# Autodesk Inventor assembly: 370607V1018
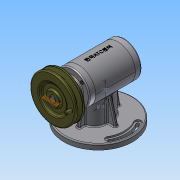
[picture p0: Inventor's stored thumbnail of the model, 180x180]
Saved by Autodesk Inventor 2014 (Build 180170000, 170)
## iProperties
Created: 2017-06
Part Number: 370607V1018
Document SubType Name: Assembly
Designer: NET
Mass: 1417.53 g
Surface Area: 1464.36 cm^2
Volume: 498.031 cm^3
Density: 2.84627 g/cm^3
Author: NET
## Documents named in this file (15)
- C:\Users\NET\Desktop\370607V1018\답안조립품.iam
- C:\Users\NET\Desktop\370607V1018\본체.ipt
- C:\Users\NET\Desktop\370607V1018\본체커버.ipt
- C:\Users\NET\Desktop\370607V1018\앞커버.ipt
- C:\Users\NET\Desktop\370607V1018\볼트 M3x0.5x8.ipt
- C:\Users\NET\Desktop\370607V1018\오일실 12 22 7.ipt
- C:\Users\NET\Desktop\370607V1018\베어링 6201.ipt
- C:\Users\NET\Desktop\370607V1018\뒤커버.ipt
- C:\Users\NET\Desktop\370607V1018\베어링 6202.ipt
- C:\Users\NET\Desktop\370607V1018\편심축.ipt
- C:\Users\NET\Desktop\370607V1018\키 4 x 4 x 18.ipt
- C:\Users\NET\Desktop\370607V1018\V-벨트풀리.ipt
- C:\Users\NET\Desktop\370607V1018\멈춤나사 M3x8.ipt
- C:\Users\NET\Desktop\370607V1018\슬라이드.ipt
- C:\Users\NET\Desktop\370607V1018\스프링.ipt
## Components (1 placed, 1 different names)
1. V-벨트풀리:1 — 강체:1
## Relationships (1: WeldJoint 1)
- 강체:1 [WeldJoint]: V-벨트풀리:1
